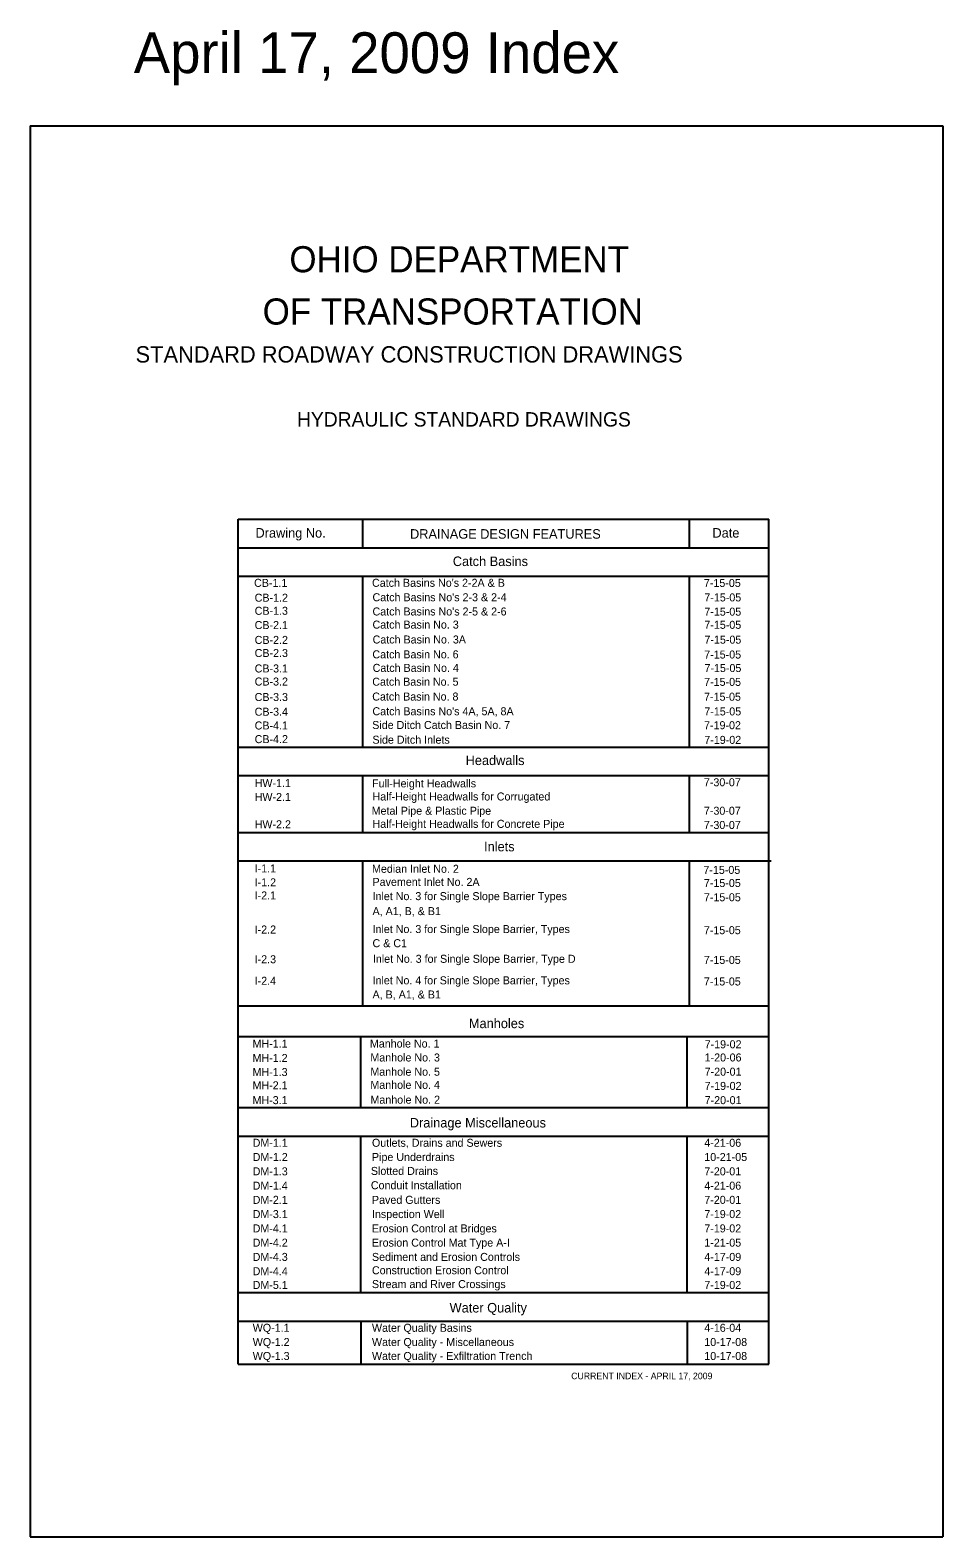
# Model space of a CAD drawing. Extents: x 146 to 619, y 56 to 2134.
# Drawn here: x 597.17 to 619.17, y 2097.9 to 2134.21 of the extents above; entities that cross this region are included whole.
import ezdxf

# ---------------------------------------------------------------- set-up
doc = ezdxf.new("R2010")
doc.units = 0
doc.layers.add('Level 1', color=7, linetype='Continuous')

msp = doc.modelspace()

# ---------------------------------------------------------------- linework, layer by layer
at = {"layer": 'Level 1'}
for p, q in [((597.168, 2131.9), (619.168, 2131.9)), ((597.168, 2131.9), (597.168, 2097.9)), ((619.168, 2131.9), (619.168, 2097.9)), ((602.185, 2102.061), (602.185, 2122.419)), ((602.185, 2122.419), (614.974, 2122.419)), ((602.185, 2122.419), (602.185, 2122.419)), ((605.188, 2121.733), (605.188, 2122.419)), ((613.058, 2121.733), (613.058, 2122.419)), ((614.974, 2102.061), (614.974, 2122.419)), ((614.974, 2122.419), (614.974, 2122.419)), ((602.185, 2121.733), (614.974, 2121.733)), ((602.185, 2121.047), (614.974, 2121.047)), ((605.188, 2116.932), (605.188, 2121.047)), ((613.058, 2116.932), (613.058, 2121.047)), ((602.185, 2116.932), (614.974, 2116.932)), ((602.185, 2116.246), (614.974, 2116.246)), ((605.188, 2114.872), (605.188, 2116.246)), ((613.058, 2114.872), (613.058, 2116.246)), ((602.185, 2114.874), (614.974, 2114.874)), ((602.185, 2114.188), (614.974, 2114.188)), ((602.237, 2114.188), (615.026, 2114.188)), ((605.188, 2114.188), (605.188, 2114.192)), ((605.188, 2110.695), (605.188, 2114.188)), ((613.058, 2114.188), (613.058, 2114.189)), ((613.058, 2110.695), (613.058, 2114.188)), ((602.185, 2110.695), (614.974, 2110.695)), ((602.185, 2109.958), (614.974, 2109.958)), ((605.137, 2108.243), (605.137, 2109.958)), ((613.007, 2108.266), (613.007, 2109.958)), ((605.137, 2108.243), (605.137, 2109.272)), ((613.007, 2108.243), (613.007, 2109.272)), ((602.185, 2108.243), (614.974, 2108.243)), ((602.185, 2107.557), (614.974, 2107.557)), ((605.137, 2106.185), (605.137, 2107.557)), ((613.007, 2106.185), (613.007, 2107.557)), ((613.007, 2104.826), (613.007, 2107.536)), ((605.137, 2104.283), (605.137, 2107.027)), ((605.137, 2103.785), (605.137, 2105.156)), ((613.007, 2103.784), (613.007, 2105.177)), ((602.185, 2103.785), (614.974, 2103.785)), ((602.185, 2103.099), (614.974, 2103.099)), ((605.137, 2103.099), (605.137, 2102.061)), ((613.007, 2103.098), (613.007, 2102.062)), ((602.185, 2102.061), (614.974, 2102.061)), ((597.168, 2097.9), (619.168, 2097.9))]:
    msp.add_line(p, q, dxfattribs=at)

# ---------------------------------------------------------------- texts
for s, height, p in [('April 17, 2009 Index', 0.98375, (599.666, 2133.169)), ('OHIO DEPARTMENT', 0.6296, (603.417, 2128.37)), ('OF TRANSPORTATION', 0.6296, (602.772, 2127.111)), ('STANDARD ROADWAY CONSTRUCTION DRAWINGS', 0.3935, (599.71, 2126.196)), ('HYDRAULIC STANDARD DRAWINGS', 0.34707, (603.601, 2124.653)), ('Drawing No.', 0.23, (602.6, 2121.977)), ('DRAINAGE DESIGN FEATURES', 0.23, (606.325, 2121.951)), ('Date', 0.23, (613.614, 2121.977)), ('Catch Basins', 0.23, (607.356, 2121.292)), ('CB-1.1', 0.1928, (602.566, 2120.791)), ("Catch Basins No's 2-2A & B", 0.1928, (605.409, 2120.792)), ('7-15-05', 0.1928, (613.408, 2120.788)), ('CB-1.2', 0.1928, (602.58, 2120.433)), ("Catch Basins No's 2-3 & 2-4", 0.1928, (605.421, 2120.444)), ('7-15-05', 0.1928, (613.419, 2120.44)), ('CB-1.3', 0.1928, (602.58, 2120.118)), ("Catch Basins No's 2-5 & 2-6", 0.1928, (605.421, 2120.101)), ('7-15-05', 0.1928, (613.419, 2120.097)), ('CB-2.1', 0.1928, (602.58, 2119.774)), ('Catch Basin No. 3', 0.1928, (605.421, 2119.785)), ('7-15-05', 0.1928, (613.419, 2119.78)), ('CB-2.2', 0.1928, (602.58, 2119.416)), ('Catch Basin No. 3A', 0.1928, (605.423, 2119.426)), ('7-15-05', 0.1928, (613.421, 2119.422)), ('CB-2.3', 0.1928, (602.58, 2119.1)), ('Catch Basin No. 6', 0.1928, (605.418, 2119.068)), ('7-15-05', 0.1928, (613.416, 2119.064)), ('CB-3.1', 0.1928, (602.58, 2118.728)), ('Catch Basin No. 4', 0.1928, (605.424, 2118.742)), ('7-15-05', 0.1928, (613.422, 2118.738)), ('CB-3.2', 0.1928, (602.58, 2118.413)), ('Catch Basin No. 5', 0.1928, (605.415, 2118.409)), ('7-15-05', 0.1928, (613.414, 2118.405)), ('CB-3.3', 0.1928, (602.58, 2118.04)), ('Catch Basin No. 8', 0.1928, (605.414, 2118.051)), ('7-15-05', 0.1928, (613.412, 2118.047)), ('CB-3.4', 0.1928, (602.58, 2117.686)), ("Catch Basins No's 4A, 5A, 8A", 0.1928, (605.419, 2117.697)), ('7-15-05', 0.1928, (613.418, 2117.693)), ('CB-4.1', 0.1928, (602.58, 2117.354)), ('Side Ditch Catch Basin No. 7', 0.1928, (605.414, 2117.366)), ('7-19-02', 0.1928, (613.412, 2117.361)), ('CB-4.2', 0.1928, (602.58, 2117.025)), ('Side Ditch Inlets', 0.1928, (605.419, 2117.011)), ('7-19-02', 0.1928, (613.418, 2117.007)), ('Headwalls', 0.23, (607.665, 2116.497)), ('HW-1.1', 0.1928, (602.58, 2115.967)), ('Full-Height Headwalls', 0.1928, (605.409, 2115.959)), ('7-30-07', 0.1928, (613.408, 2115.986)), ('HW-2.1', 0.1928, (602.58, 2115.632)), ('Half-Height Headwalls for Corrugated ', 0.1928, (605.421, 2115.643)), ('       Metal Pipe & Plastic Pipe', 0.1928, (604.898, 2115.3)), ('Half-Height Headwalls for Concrete Pipe', 0.1928, (605.421, 2114.984)), ('7-30-07', 0.1928, (613.408, 2115.3)), ('HW-2.2', 0.1928, (602.58, 2114.974)), ('7-30-07', 0.1928, (613.408, 2114.957)), ('Inlets', 0.23, (608.11, 2114.418)), ('I-1.1', 0.1928, (602.58, 2113.91)), ('Median Inlet No. 2', 0.1928, (605.409, 2113.901)), ('I-1.2', 0.1928, (602.58, 2113.574)), ('Pavement Inlet No. 2A', 0.1928, (605.421, 2113.585)), ('7-15-05', 0.1928, (613.396, 2113.874)), ('7-15-05', 0.1928, (613.408, 2113.558)), ('I-2.1', 0.1928, (602.58, 2113.259)), ('Inlet No. 3 for Single Slope Barrier Types ', 0.1928, (605.421, 2113.242)), ('7-15-05', 0.1928, (613.408, 2113.215)), ('A, A1, B, & B1', 0.1928, (605.421, 2112.881)), ('I-2.2', 0.1928, (602.58, 2112.438)), ('Inlet No. 3 for Single Slope Barrier, Types', 0.1928, (605.421, 2112.449)), ('C & C1', 0.1928, (605.421, 2112.108)), ('7-15-05', 0.1928, (613.407, 2112.422)), ('I-2.3', 0.1928, (602.58, 2111.721)), ('Inlet No. 3 for Single Slope Barrier, Type D', 0.1928, (605.429, 2111.732)), ('7-15-05', 0.1928, (613.407, 2111.705)), ('I-2.4', 0.1928, (602.58, 2111.202)), ('Inlet No. 4 for Single Slope Barrier, Types', 0.1928, (605.421, 2111.213)), ('7-15-05', 0.1928, (613.407, 2111.186)), ('A, B, A1, & B1', 0.1928, (605.421, 2110.872)), ('Manholes', 0.23, (607.744, 2110.158)), ('MH-1.1', 0.1928, (602.528, 2109.687)), ('Manhole No. 1', 0.1928, (605.358, 2109.69)), ('7-19-02', 0.1928, (613.426, 2109.672)), ('MH-1.2', 0.1928, (602.528, 2109.343)), ('Manhole No. 3', 0.1928, (605.369, 2109.354)), ('1-20-06', 0.1928, (613.426, 2109.355)), ('MH-1.3', 0.1928, (602.528, 2109.003)), ('Manhole No. 5', 0.1928, (605.369, 2109.011)), ('7-20-01', 0.1928, (613.426, 2109.012)), ('MH-2.1', 0.1928, (602.528, 2108.684)), ('Manhole No. 4', 0.1928, (605.369, 2108.695)), ('7-19-02', 0.1928, (613.426, 2108.669)), ('MH-3.1', 0.1928, (602.528, 2108.326)), ('Manhole No. 2', 0.1928, (605.371, 2108.337)), ('7-20-01', 0.1928, (613.426, 2108.326)), ('Drainage Miscellaneous', 0.23, (606.319, 2107.764)), ('DM-1.1', 0.1928, (602.532, 2107.299)), ('Outlets, Drains and Sewers', 0.1928, (605.407, 2107.299)), ('4-21-06', 0.1928, (613.418, 2107.299)), ('DM-1.2', 0.1928, (602.532, 2106.956)), ('Slotted Drains', 0.1928, (605.381, 2106.621)), ('Pipe Underdrains', 0.1928, (605.407, 2106.956)), ('10-21-05', 0.1928, (613.418, 2106.956)), ('DM-1.3', 0.1928, (602.532, 2106.611)), ('DM-1.4', 0.1928, (602.532, 2106.266)), ('Conduit Installation', 0.1928, (605.381, 2106.276)), ('4-21-06', 0.1928, (613.418, 2106.266)), ('7-20-01', 0.1928, (613.418, 2106.611)), ('DM-2.1', 0.1928, (602.532, 2105.924)), ('Paved Gutters', 0.1928, (605.407, 2105.924)), ('7-20-01', 0.1928, (613.418, 2105.924)), ('DM-3.1', 0.1928, (602.532, 2105.581)), ('Inspection Well', 0.1928, (605.407, 2105.581)), ('7-19-02', 0.1928, (613.418, 2105.581)), ('DM-4.1', 0.1928, (602.532, 2105.236)), ('Erosion Control at Bridges', 0.1928, (605.407, 2105.236)), ('7-19-02', 0.1928, (613.418, 2105.236)), ('DM-4.2', 0.1928, (602.532, 2104.893)), ('Erosion Control Mat Type A-I', 0.1928, (605.407, 2104.893)), ('1-21-05', 0.1928, (613.418, 2104.893)), ('DM-4.3', 0.1928, (602.532, 2104.549)), ('Sediment and Erosion Controls', 0.1928, (605.407, 2104.549)), ('4-17-09', 0.1928, (613.418, 2104.549)), ('DM-4.4', 0.1928, (602.532, 2104.204)), ('Construction Erosion Control', 0.1928, (605.407, 2104.227)), ('4-17-09', 0.1928, (613.418, 2104.204)), ('DM-5.1', 0.1928, (602.532, 2103.873)), ('Stream and River Crossings', 0.1928, (605.407, 2103.894)), ('7-19-02', 0.1928, (613.418, 2103.873)), ('Water Quality', 0.23, (607.279, 2103.306)), ('WQ-1.1', 0.1928, (602.533, 2102.841)), ('Water Quality Basins', 0.1928, (605.407, 2102.841)), ('4-16-04', 0.1928, (613.418, 2102.841)), ('WQ-1.2', 0.1928, (602.533, 2102.498)), ('Water Quality - Miscellaneous', 0.1928, (605.407, 2102.498)), ('10-17-08', 0.1928, (613.418, 2102.498)), ('WQ-1.3', 0.1928, (602.533, 2102.162)), ('Water Quality - Exfiltration Trench', 0.1928, (605.407, 2102.162)), ('10-17-08', 0.1928, (613.418, 2102.162)), ('CURRENT INDEX - APRIL 17, 2009', 0.1574, (610.209, 2101.698))]:
    msp.add_text(s, height=height, dxfattribs=at).set_placement(p)

doc.saveas('drawing.dxf')
